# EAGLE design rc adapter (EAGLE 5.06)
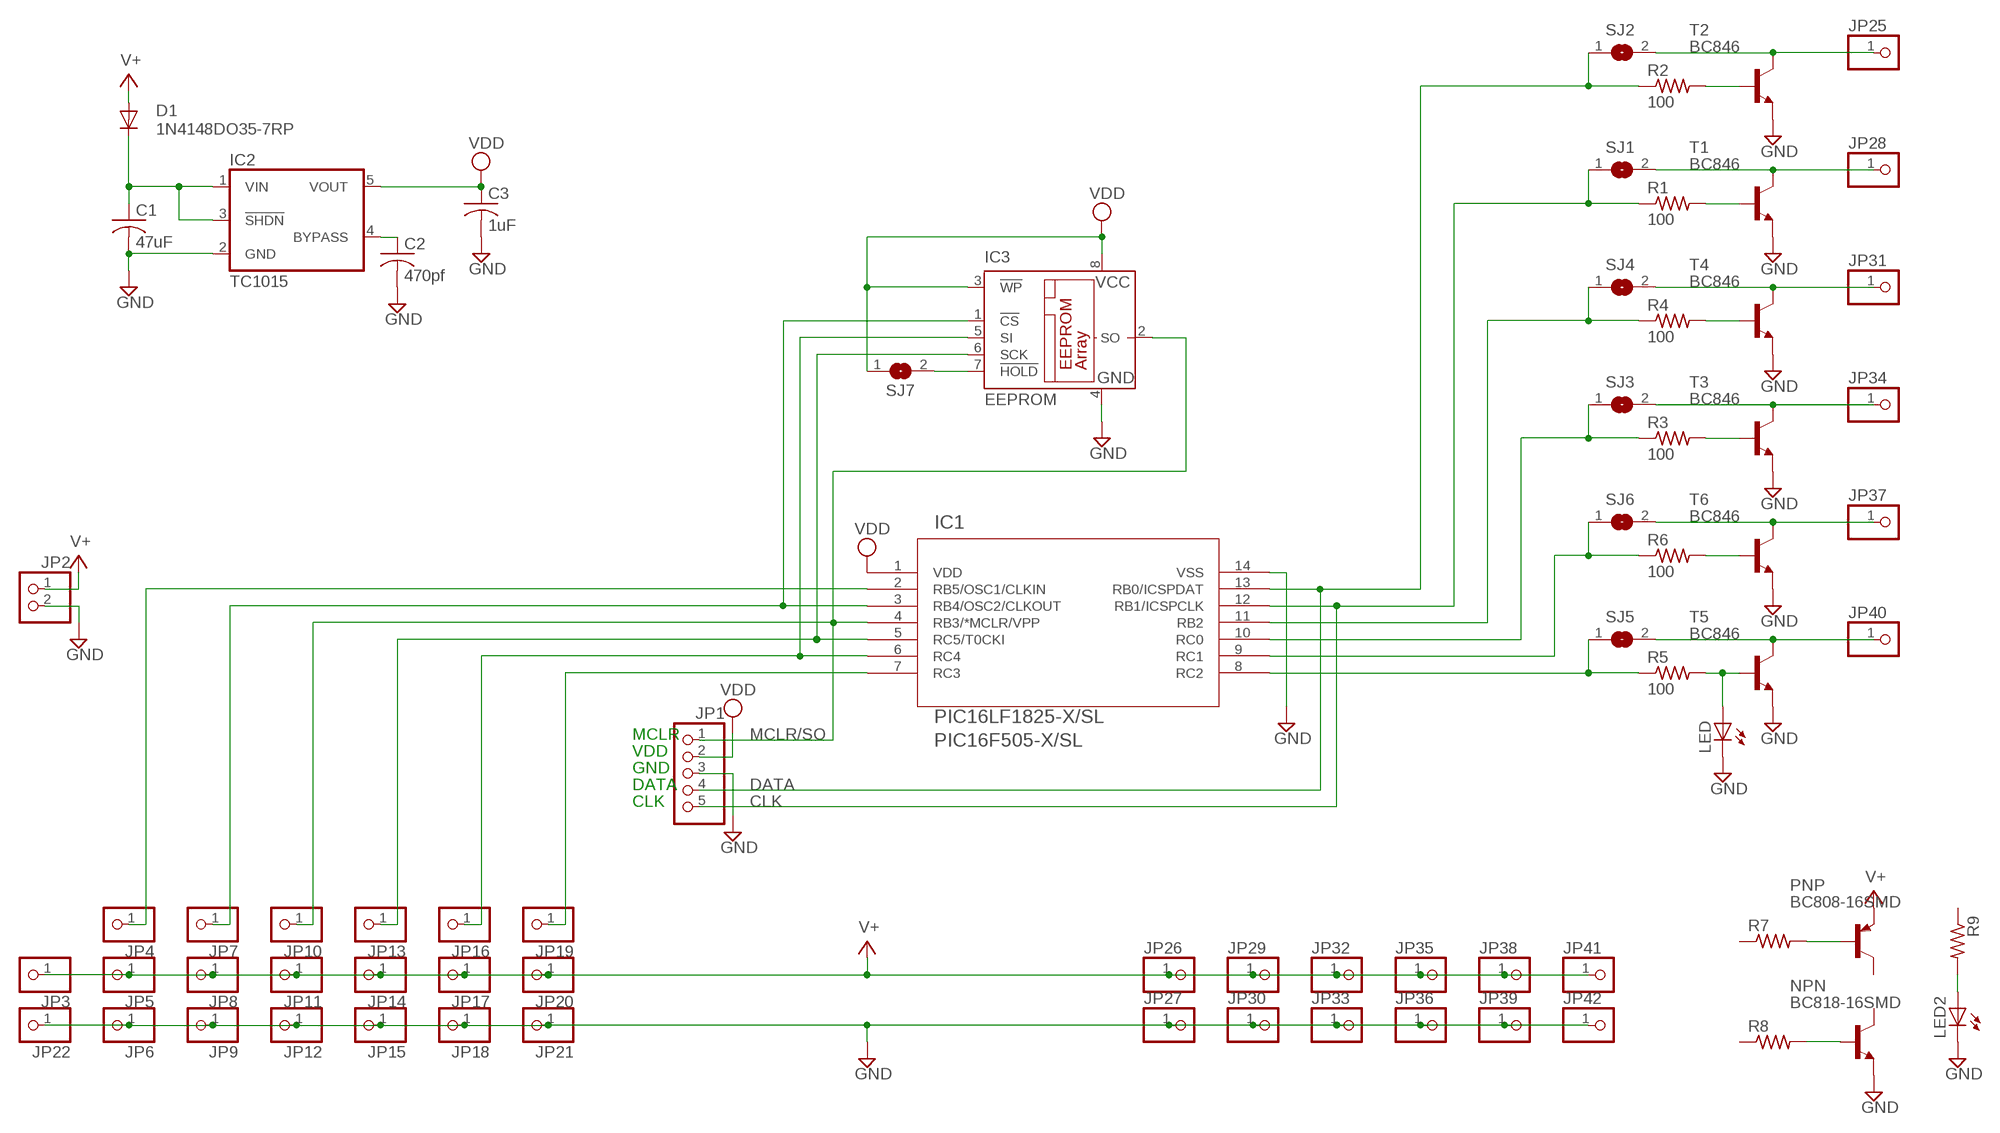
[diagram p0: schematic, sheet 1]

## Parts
C1  47uF  C-USC1210  [C1210]
C2  470pf  C-USC0805  [C0805]
C3  1uF  C-USC0805  [C0805]
D1  1N4148DO35-7RP  [D-7.5-ROUNDPAD]
IC1  PIC16F505-X/SL  [SOIC14-N_MC]
IC2  TC1015  [SOT25]
IC3  EEPROM  25AA080SN  [SO-08]
JP1  PINHD-1X5  [1X05]
JP2  PINHD-1X2  [1X02]
JP3  PINHD-1X1  [1X01]
JP4  PINHD-1X1  [1X01]
JP5  PINHD-1X1  [1X01]
JP6  PINHD-1X1  [1X01]
JP7  PINHD-1X1  [1X01]
JP8  PINHD-1X1  [1X01]
JP9  PINHD-1X1  [1X01]
JP10  PINHD-1X1  [1X01]
JP11  PINHD-1X1  [1X01]
JP12  PINHD-1X1  [1X01]
JP13  PINHD-1X1  [1X01]
JP14  PINHD-1X1  [1X01]
JP15  PINHD-1X1  [1X01]
JP16  PINHD-1X1  [1X01]
JP17  PINHD-1X1  [1X01]
JP18  PINHD-1X1  [1X01]
JP19  PINHD-1X1  [1X01]
JP20  PINHD-1X1  [1X01]
JP21  PINHD-1X1  [1X01]
JP22  PINHD-1X1  [1X01]
JP25  PINHD-1X1  [1X01]
JP26  PINHD-1X1  [1X01]
JP27  PINHD-1X1  [1X01]
JP28  PINHD-1X1  [1X01]
JP29  PINHD-1X1  [1X01]
JP30  PINHD-1X1  [1X01]
JP31  PINHD-1X1  [1X01]
JP32  PINHD-1X1  [1X01]
JP33  PINHD-1X1  [1X01]
JP34  PINHD-1X1  [1X01]
JP35  PINHD-1X1  [1X01]
JP36  PINHD-1X1  [1X01]
JP37  PINHD-1X1  [1X01]
JP38  PINHD-1X1  [1X01]
JP39  PINHD-1X1  [1X01]
JP40  PINHD-1X1  [1X01]
JP41  PINHD-1X1  [1X01]
JP42  PINHD-1X1  [1X01]
LED  LEDCHIPLED_0805  [CHIPLED_0805]
LED2  LEDCHIPLED_0805  [CHIPLED_0805]
NPN  BC818-16SMD  [SOT23-BEC]
PNP  BC808-16SMD  [SOT23-BEC]
R1  100  R-US_R1206  [R1206]
R2  100  R-US_R1206  [R1206]
R3  100  R-US_R1206  [R1206]
R4  100  R-US_R1206  [R1206]
R5  100  R-US_R1206  [R1206]
R6  100  R-US_R1206  [R1206]
R7  R-US_R0805  [R0805]
R8  R-US_R0805  [R0805]
R9  R-US_R0805  [R0805]
SJ1  SJ  [SJ]
SJ2  SJ  [SJ]
SJ3  SJ  [SJ]
SJ4  SJ  [SJ]
SJ5  SJ  [SJ]
SJ6  SJ  [SJ]
SJ7  SJSMALL  [SJ-SMALL]
T1  BC846  [SOT23]
T2  BC846  [SOT23]
T3  BC846  [SOT23]
T4  BC846  [SOT23]
T5  BC846  [SOT23]
T6  BC846  [SOT23]

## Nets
BYPASS: C2.1 IC2.4(BYPASS)
CLK: IC1.12(RB1/ICSPCLK) JP1.5 R1.1 SJ1.1
DATA: IC1.13(RB0/ICSPDAT) JP1.4 R2.1 SJ2.1
EEPROM_CS: IC1.3(RB4/OSC2/CLKOUT) IC3.1(!CS) JP7.1
EEPROM_SCLK: IC1.5(RC5/T0CKI) IC3.6(SCK) JP13.1
EEPROM_SI: IC1.6(RC4) IC3.5(SI) JP16.1
GND: C1.2 C2.2 C3.2 IC1.14(VSS) IC2.2(GND) IC3.4(GND) JP1.3 JP2.2 JP6.1 JP9.1 JP12.1 JP15.1 JP18.1 JP21.1 JP22.1 JP27.1 JP30.1 JP33.1 JP36.1 JP39.1 JP42.1 LED2.C LED.C NPN.E T1.2(E) T2.2(E) T3.2(E) T4.2(E) T5.2(E) T6.2(E)
MCLR/SO: IC1.4(RB3/*MCLR/VPP) IC3.2(SO) JP1.1 JP10.1
N$1: IC1.2(RB5/OSC1/CLKIN) JP4.1
N$2: PNP.B R7.2
N$3: R1.2 T1.1(B)
N$4: NPN.B R8.2
N$5: IC1.7(RC3) JP19.1
N$7: IC1.8(RC2) R5.1 SJ5.1
N$8: IC1.9(RC1) R6.1 SJ6.1
N$9: IC1.10(RC0) R3.1 SJ3.1
N$10: IC1.11(RB2) R4.1 SJ4.1
N$11: R2.2 T2.1(B)
N$12: R3.2 T3.1(B)
N$13: R4.2 T4.1(B)
N$14: LED.A R5.2 T5.1(B)
N$15: R6.2 T6.1(B)
N$16: JP28.1 SJ1.2 T1.3(C)
N$17: JP25.1 SJ2.2 T2.3(C)
N$18: JP34.1 SJ3.2 T3.3(C)
N$20: JP40.1 SJ5.2 T5.3(C)
N$21: JP37.1 SJ6.2 T6.3(C)
N$22: IC3.7(!HOLD) SJ7.2
N$23: LED2.A R9.2
N$26: JP31.1 SJ4.2 T4.3(C)
V+: D1.A JP2.1 JP3.1 JP5.1 JP8.1 JP11.1 JP14.1 JP17.1 JP20.1 JP26.1 JP29.1 JP32.1 JP35.1 JP38.1 JP41.1 PNP.E
VDD: C3.1 IC1.1(VDD) IC2.5(VOUT) IC3.3(!WP) IC3.8(VCC) JP1.2 SJ7.1
VPWR: C1.1 D1.C IC2.1(VIN) IC2.3(!SHDN)
Unconnected: NPN.C PNP.C R7.1 R8.1 R9.1

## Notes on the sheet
- PIC16LF1825-X/SL
- MCLR
- VDD
- GND
- DATA
- CLK

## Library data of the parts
C1-C3 = rcl:C-US: CAPACITOR, American symbol
D1 = diode:1N4148: DIODE
IC1 = mylib:PIC16F505-X/SL
IC2 = mylib:TC1015: 150mA Low Noise LDO Voltage Regulator
IC3 = microchip:25*: Serial EEPROM 4 K, SPI bus
JP1 = pinhead:PINHD-1X5: PIN HEADER
JP2 = pinhead:PINHD-1X2: PIN HEADER
JP3-JP22 JP25-JP42 = pinhead:PINHD-1X1: PIN HEADER
LED LED2 = led:LED: LED
NPN = transistor-npn:BC818*: NPN Transistor
PNP = transistor-pnp:BC808*: PNP Transistror
R1-R9 = rcl:R-US_: RESISTOR, American symbol
SJ1-SJ7 = jumper:SJ: SMD solder JUMPER
T1-T6 = transistor:BC846: NPN TRANSISTOR

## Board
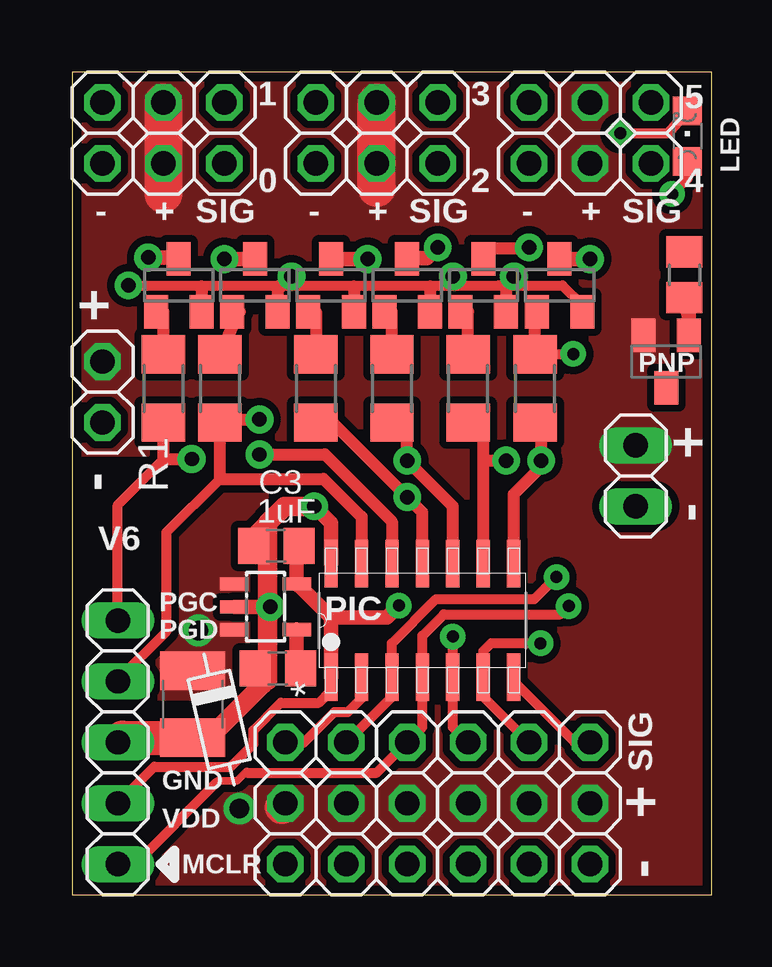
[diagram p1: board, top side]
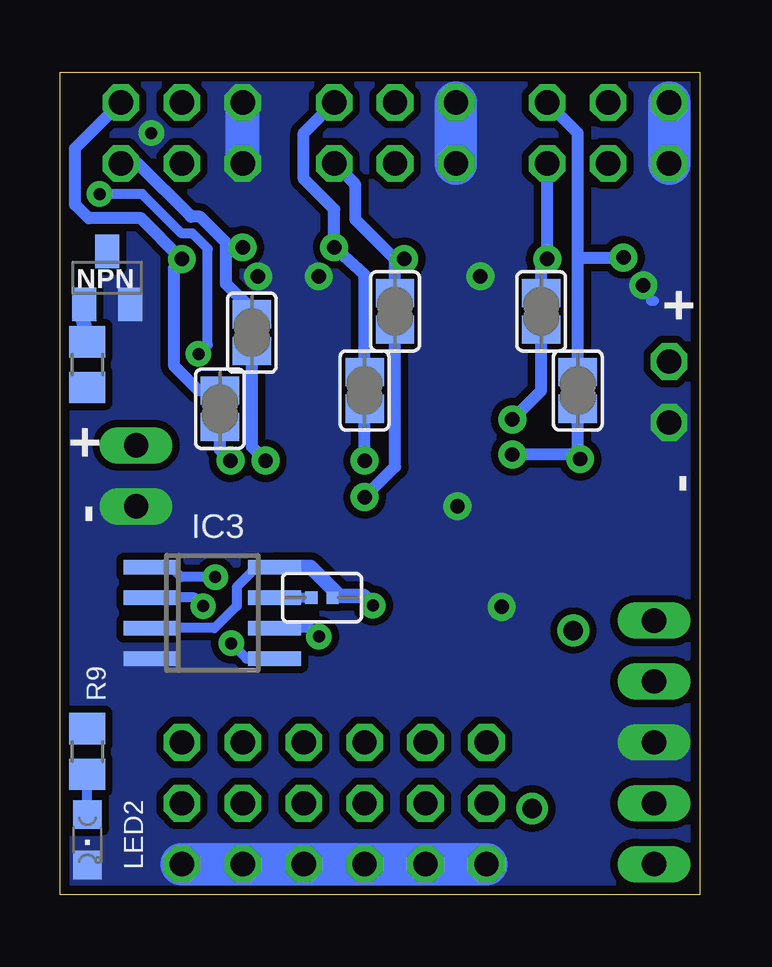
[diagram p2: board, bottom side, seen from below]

Size 26.67 x 34.29 mm. Coordinates in mm from the lower left corner, seen from the top.
Outline: 0,0 26.67,0 26.67,34.29 0,34.29 0,0
Copper layers (1*16): Top 0.0356mm / dielectric 1.5011mm / Bottom 0.0356mm
Design rules "LaenPCBOrder *": minimum track width 6mil, minimum drill 13mil, track to track 7mil, track to pad 7mil, pad to pad 6mil, via to via 7mil, smd to smd 6mil, copper to edge 15mil, drill to drill 6mil, minimum pad ring 10mil, minimum via ring 11mil, stop-mask expansion 4mil, vias tented up to drill 0mil, thermal gap 10mil

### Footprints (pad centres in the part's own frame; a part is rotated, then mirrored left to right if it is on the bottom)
C1210 = smd 1.6 x 2.7: 1 -1.4,0; 2 1.4,0
C0805 = smd 1.3 x 1.5: 1 -0.95,0; 2 0.95,0
D-7.5-ROUNDPAD = drill 0.813 round: A 3.81,0; C -3.81,0
SOIC14-N_MC = smd 1.981 x 0.559: 1 -2.362,3.81; 2 -2.362,2.54; 3 -2.362,1.27; 4 -2.362,0; 5 -2.362,-1.27; 6 -2.362,-2.54; 7 -2.362,-3.81; 8 2.362,-3.81; 9 2.362,-2.54; 10 2.362,-1.27; 11 2.362,0; 12 2.362,1.27; 13 2.362,2.54; 14 2.362,3.81
SOT25 = smd 0.55 x 1.2: 1 -0.95,-1.3; 2 0,-1.3; 3 0.95,-1.3; 4 0.95,1.3; 5 -0.95,1.3
SO-08 = smd 0.6 x 2.2: 1 -1.905,-2.6; 2 -0.635,-2.6; 3 0.635,-2.6; 4 1.905,-2.6; 5 1.905,2.6; 6 0.635,2.6; 7 -0.635,2.6; 8 -1.905,2.6
1X05 = drill 1.016 long: 1 -5.08,0; 2 -2.54,0; 3 0,0; 4 2.54,0; 5 5.08,0
1X02 = drill 1.016 long: 1 -1.27,0; 2 1.27,0
1X01 = drill 1.016 octagon: 1 0,0
CHIPLED_0805 = smd 1.2 x 1.2: A 0,-1.05; C 0,1.05
SOT23-BEC = smd 1 x 1.4: B -0.95,-1.1; C 0,1.1; E 0.95,-1.1
R1206 = smd 1.6 x 1.803: 1 -1.422,0; 2 1.422,0
R0805 = smd 1.3 x 1.5: 1 -0.95,0; 2 0.95,0
SJ = smd 1.168 x 1.6: 1 -0.762,0; 2 0.762,0
SJ-SMALL = smd 0.508 x 0.508: 1 -0.445,0; 2 0.445,0
SOT23 = smd 1 x 1.4: 1 -0.95,-1.1; 2 0.95,-1.1; 3 0,1.1

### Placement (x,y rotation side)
C1  5.03,7.94 270 top
C2  8.57,9.44 180 top
C3  8.51,14.54 180 top
D1  6.12,7.3 283 top
IC1  14.61,11.43 90 top
IC2  8.06,12 270 top
IC3  20.32,11.75 270 bottom
JP1  1.91,6.35 90 top
JP2  23.5,17.46 270 top
JP3  1.27,22.23 0 top
JP4  8.89,6.35 0 top
JP5  8.89,3.81 90 top
JP6  8.89,1.27 0 top
JP7  11.43,6.35 0 top
JP8  11.43,3.81 0 top
JP9  11.43,1.27 0 top
JP10  13.97,6.35 0 top
JP11  13.97,3.81 0 top
JP12  13.97,1.27 0 top
JP13  16.51,6.35 0 top
JP14  16.51,3.81 0 top
JP15  16.51,1.27 0 top
JP16  19.05,6.35 0 top
JP17  19.05,3.81 0 top
JP18  19.05,1.27 0 top
JP19  21.59,6.35 0 top
JP20  21.59,3.81 0 top
JP21  21.59,1.27 0 top
JP22  1.27,19.68 0 top
JP25  6.35,30.48 0 top
JP26  3.81,33.02 0 top
JP27  1.27,33.02 0 top
JP28  6.35,33.02 0 top
JP29  12.7,33.02 0 top
JP30  10.16,33.02 0 top
JP31  15.24,30.48 0 top
JP32  21.59,33.02 0 top
JP33  19.05,33.02 0 top
JP34  15.24,33.02 0 top
JP35  3.81,30.48 0 top
JP36  1.27,30.48 0 top
JP37  24.13,30.48 0 top
JP38  12.7,30.48 0 top
JP39  10.16,30.48 0 top
JP40  24.13,33.02 0 top
JP41  21.59,30.48 0 top
JP42  19.05,30.48 0 top
LED  25.65,31.62 0 top
LED2  25.53,2.29 180 bottom
NPN  24.7,25.72 0 bottom
PNP  24.77,22.23 180 top
R1  3.81,21.11 90 top
R2  6.16,21.11 90 top
R3  13.34,21.11 90 top
R4  10.16,21.11 90 top
R5  19.3,21.11 90 top
R6  16.51,21.11 90 top
R7  25.53,25.84 270 top
R8  25.53,22.1 90 bottom
R9  25.53,5.97 270 bottom
SJ1  5.08,21.02 90 bottom
SJ2  6.6,24.32 90 bottom
SJ3  13.97,21.02 90 bottom
SJ4  12.7,24.32 90 bottom
SJ5  20,20.26 90 bottom
SJ6  18.67,23.43 90 bottom
SJ7  15.75,12.38 180 bottom
T1  4.45,25.4 0 top
T2  7.62,25.4 0 top
T3  13.97,25.4 0 top
T4  10.79,25.4 0 top
T5  20.32,25.4 0 top
T6  17.14,25.4 0 top

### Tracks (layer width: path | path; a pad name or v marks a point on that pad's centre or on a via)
BYPASS
  Top 0.61: IC2.4 9.36,9.34 C2.1
CLK  (via drill 0.6)
  Top 0.406: JP1.5 1.91,16.26 3.81,18.16
  Top 0.508: IC1.12 13.34,15.56 10.54,18.35 v7.81,18.35 | v4.99,18.16 3.81,18.16 R1.1
  Bottom 0.508: v7.81,18.35 5.17,18.35 v4.99,18.16 5.08,18.26 SJ1.1
DATA  (via drill 0.6)
  Top 0.305: JP1.4 1.91,8.95
  Top 0.406: 1.91,8.95 3.94,10.99 3.94,15.11 6.16,17.34 | R2.1
  Top 0.508: IC1.13 12.06,15.75 10.48,17.34 6.16,17.34 R2.1 6.16,19.81 v7.81,19.81
  Bottom 0.508: SJ2.1 6.6,21.02 v7.81,19.81
EEPROM_CS  (via drill 0.5)
  Top 0.406: JP7.1 13.34,8.26 IC1.3 13.34,10.48 15.18,12.32 19.27,12.32 v20.19,13.24
  Bottom 0.406: v20.19,13.24 21.62,13.24 22.04,13.65 IC3.1
EEPROM_SCLK  (via drill 0.5)
  Top 0.406: JP13.1 15.88,6.99 IC1.5 v15.88,10.76
  Bottom 0.406: IC3.6 16.22,11.11 v15.88,10.76
EEPROM_SI  (via drill 0.5)
  Top 0.406: JP16.1 17.14,8.26 IC1.6 17.14,10.16 17.46,10.48 v19.53,10.48
  Bottom 0.406: IC3.5 18.89,9.84 v19.53,10.48
GND  (via drill 0.5, 0.6)
  Top 0.406: 8.64,25.4 9.14,25.4 | 17.78,25.4 18.54,25.4 | 18.54,25.4 v18.41,25.78 | 9.14,25.4 v9.14,25.78 | 8.64,25.4 8.57,25.4 | 11.75,25.4 14.92,25.4 | 14.92,25.4 15.88,25.4 | 15.88,25.4 17.78,25.4 | 17.78,25.4 18.09,25.4 | v2.35,25.4 5.4,25.4 | 5.4,25.4 8.64,25.4 | 18.54,25.4 20.45,25.4 21.25,24.59 21.25,24.3 | 15.88,25.4 v15.88,25.78 | 14.92,25.4 14.92,25.34 | 11.75,25.4 11.75,25.34 | 9.14,25.4 11.75,25.4 | 5.39,25.34 5.4,24.89 5.4,25.4 | LED.C 24.86,31.75 v22.86,31.75
  Top 0.508: 21.25,24.3 T5.2 | T6.2 18.09,25.33 v18.41,25.78 | T2.2 8.57,25.21 v9.14,25.78 | 14.92,25.34 T3.2 | T4.2 11.74,25.27 11.75,25.34 | 5.39,25.34 T1.2
  Top 0.559: 7.56,14.48 C3.2 | 8.15,14.86 8.26,14.8
  Top 0.61: v8.26,12 IC2.2 | 8.15,11.75 v8.26,12 | C2.2 8.15,8.93 | v8.26,12 8.15,12.19 | v10.1,16.19 10.79,15.49 IC1.14
  Top 0.813: 8.15,8.93 8.15,11.75 | 7.56,14.48 8.15,14.9 8.15,14.86 | 8.15,12.19 8.15,14.86 | C1.2 5.71,6.54 7.94,8.76 | 8.15,14.86 8.15,15.49 8.85,16.19 | 8.85,16.19 v10.1,16.19 | 8.85,16.19 7.62,14.96 7.62,14.61
  Top 1.422: C1.2 2.1,6.54 JP1.3
  Bottom 0.406: v9.14,25.78 8.89,26.04 | 1.91,24.77 2.03,24.77 | 25.18,1.27 LED2.C
  Bottom 1.27: JP9.1 11.75,1.27
  Bottom 1.422: JP42.1 JP33.1
  Bottom 1.778: JP6.1 JP9.1 JP12.1 JP15.1 JP18.1 JP21.1 | JP36.1 JP27.1 | JP39.1 JP30.1
  pour Bottom (isolate 0.305, no thermals): -1.27,35.05 27.94,35.05 27.94,-1.27 -1.27,-1.27
MCLR/SO  (via drill 0.5)
  Top 0.305: 7.49,5.08 7.28,5.08 7.21,5.08 6.87,4.74 6.06,4.74 6.03,4.67
  Top 0.406: 7.28,5.08 12.7,5.08 JP10.1 14.61,6.99 IC1.4 14.61,10.79 15.49,11.68 20.35,11.68 v20.7,12.03 | JP1.1 2.63,1.27 6.03,4.67
  Bottom 0.406: v20.7,12.03 21.05,12.38 IC3.2
N$1
  Top 0.406: 12.06,8.89 IC1.2 12.06,8.19 11.49,7.62 10.94,7.62 9.66,6.35 JP4.1
N$2
  Top 0.61: PNP.B 25.71,24.17 R7.2
N$3
  Top 0.406: 3.81,24.3 T1.1
  Top 0.508: R1.2 3.81,24.3
N$4
  Bottom 0.61: NPN.B 25.71,24.09 R8.2
N$5
  Top 0.406: JP19.1 20.95,6.35 18.41,8.89 IC1.7
N$7  (via drill 0.6)
  Top 0.508: IC1.8 18.41,16.7 19.56,17.84 v19.56,18.1 19.56,19.37 R5.1 | R5.1
  Bottom 0.508: v19.56,18.1 20,18.54 SJ5.1
N$8  (via drill 0.6)
  Top 0.508: 17.14,18.1 v18.1,18.1 | 17.14,18.1 17.14,19.05 R6.1 | IC1.9 17.14,18.1
  Bottom 0.508: v18.1,18.1 18.67,18.67 SJ6.1
N$9  (via drill 0.6)
  Top 0.508: IC1.10 15.88,16.19 v13.97,18.1 13.97,19.05 R3.1
  Bottom 0.508: v13.97,18.1 SJ3.1
N$10  (via drill 0.6)
  Top 0.508: R4.1 10.6,19.68 10.86,19.68 v13.97,16.57 14.61,15.94 IC1.11
  Bottom 0.508: 12.57,23.56 SJ4.1 12.7,17.84 v13.97,16.57
N$11
  Top 0.406: 6.99,24.3 T2.1
  Top 0.508: R2.2 6.99,24.3
N$12
  Top 0.406: 13.34,24.3 T3.1
  Top 0.508: R3.2 13.34,24.3
N$13
  Top 0.406: T4.1 10.16,24.3
  Top 0.508: 10.16,24.3 R4.2
N$14  (via drill 0.5)
  Top 0.406: 19.3,24.3 T5.1 | v25.02,29.21 25.65,29.84 LED.A | v20.89,22.54 19.32,22.54 R5.2
  Top 0.508: R5.2 19.3,24.3
  Bottom 0.406: v25.02,29.21 23.24,29.21 21.59,27.56 21.14,27.56 20.51,26.92 20.51,22.92 v20.89,22.54
N$15
  Top 0.406: 16.51,24.3 T6.1
  Top 0.508: R6.2 16.51,24.3
N$16  (via drill 0.6)
  Top 0.61: v3.17,26.56 4.45,26.56 T1.3
  Bottom 0.508: JP28.1 5.08,31.75 5.08,26.56 | 5.08,26.56 v3.17,26.56 | SJ1.2 5.08,26.56
N$17  (via drill 0.6)
  Top 0.61: v6.35,26.5 T2.3
  Bottom 0.508: JP25.1 v6.35,26.5 6.6,26.25 SJ2.2
N$18  (via drill 0.6)
  Top 0.508: T3.3 14.01,26.54 14.03,26.54
  Top 0.61: 14.03,26.54 14.8,26.54 v15.24,26.99
  Bottom 0.406: JP34.1 15.24,32.99
  Bottom 0.508: JP34.1 16.51,31.75 16.51,29.84 15.24,28.57 v15.24,26.99 13.97,25.84 SJ3.2
N$20  (via drill 0.6)
  Top 0.61: v21.59,26.5 T5.3
  Bottom 0.508: JP40.1 26.04,31.11 26.04,28.77 25.46,28.19 23.28,28.19 v21.59,26.5 21.91,26.18 21.91,22.04 20.89,21.02 SJ5.2
N$21  (via drill 0.6)
  Top 0.305: 17.36,26.94 T6.3
  Top 0.508: T6.3 17.25,26.54 | v19.05,26.99 18.8,26.94 17.36,26.94
  Bottom 0.508: JP37.1 23.43,30.48 21.21,28.26 20.83,28.26 19.75,27.18 19.75,26.92 | SJ6.2 18.67,24.38 19.75,25.46 19.75,26.92 | v19.05,26.99 19.68,26.99 19.75,26.92
N$22
  Bottom 0.406: IC3.7 SJ7.2
N$23
  Bottom 0.406: LED2.A R9.2
N$26  (via drill 0.6)
  Top 0.61: v12.32,26.5 T4.3
  Bottom 0.508: SJ4.2 12.7,26.5 | 12.7,26.5 v12.32,26.5 | 12.7,26.5 14.35,28.15 14.35,29.59 JP31.1
V+
  Top 1.422: JP5.1 8.73,3.65
  Top 1.575: JP29.1 JP38.1 12.7,29.46 | JP26.1 JP35.1 3.81,29.21
  pour Top (isolate 0.305, no thermals): -0.64,35.05 -0.64,18.41 10.99,18.41 10.99,7.62 1.27,7.62 1.27,0 27.3,0 27.3,35.05
VDD  (via drill 0.5)
  Top 0.406: IC1.1 10.79,8.51 10.29,8 8.7,8 7.56,6.86 7.56,6.29 6.6,5.33 3.43,5.33 JP1.2
  Top 0.61: C3.1 9.36,14.83 IC2.5 9.55,12.8 10.79,11.56 | IC1.1 10.79,11.56 | 10.79,11.56 13.13,11.56 v13.62,12.05
  Bottom 0.406: IC3.8 18.48,13.65 19.3,12.83 19.3,12.03 20.23,11.11 IC3.3 | SJ7.1 13.95,12.38 v13.62,12.05
  Bottom 0.61: IC3.8 16.22,13.65 15.02,12.45 14.01,12.45 v13.62,12.05
VPWR
  pour Top (isolate 0.305, no thermals): 0.57,8.26 0.57,17.78 10.16,17.78 10.16,8.26

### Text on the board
tNames: 1 | 3 | 5 | 0 | 2 | 4 | - | + | SIG | - | + | SIG | - | + | SIG | + | + | - | - | V6 | PGC | PGD | PIC | SIG | GND | VDD | + | MCLR | -
bNames: + | + | - | -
